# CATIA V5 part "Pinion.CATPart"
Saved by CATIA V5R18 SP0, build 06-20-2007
Part number: Part3
Bounding box of the stored display mesh (mm): x -15 to 0, y -25 to 25, z 10.489 to 60.125
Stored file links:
  D:\shriniwas\v5_r19\c16_CAT_v5r19\c16_Part\Rack Joint\Pinion.CATPart
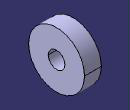
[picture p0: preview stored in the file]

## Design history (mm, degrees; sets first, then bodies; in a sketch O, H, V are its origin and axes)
Body1 (main body)
  Sketch1 on yz-plane, origin (0, 0, 0), H (0, 1, 0), V (0, 0, 1)
    reference intersected line E1 through (0, 0) direction (-1, 0) from xy-plane
    reference intersected line E3 through (0, 0) direction (0, 1) from zx-plane
    reference intersected line E4 through (0, 0) direction (-1, 0) from xy-plane
    reference intersected line E6 through (0, 0) direction (0, 1) from zx-plane
    reference intersected line E7 through (0, 0) direction (-1, 0) from xy-plane
    reference intersected line E9 through (0, 0) direction (0, 1) from zx-plane
    circle A1 centre (0, 35.3069) radius 25
    point P1 (0, 35.3069)
    circle A2 centre (0, 35.3069) radius 7.5
    radius A1 = 25
    radius A2 = 7.5
    vertical: E3 V, E6 V, E9 V
    horizontal: E1 H, E4 H, E7 H
    coincidence: P1 V
  Pad1: profile Sketch1, direction (1, 0, 0), length -15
